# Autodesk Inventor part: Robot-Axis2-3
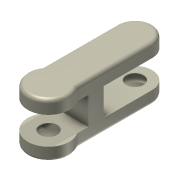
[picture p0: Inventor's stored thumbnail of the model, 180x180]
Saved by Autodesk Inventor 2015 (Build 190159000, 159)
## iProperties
Shininess: 21.0
Length Units: 11269
Angle Units: 11279
Time Units: 11290
Mass Units: 11283
Length Display Precision: 3
Angle Display Precision: 2
Created: 2001-08
Part Number: Robot-Axis2-3
Document SubType Name: ﾓﾃﾞﾘﾝｸﾞ
Designer: Administrator
Density: 1 g/cm^3
Material: Generic
Appearance: Smooth - Ivory
Density: 0.0
Volumn: 0.0
Area: 0.0
PropertySet Name: Model Information
Control State: 0
Master: False
Checked Out: False
Author: Administrator
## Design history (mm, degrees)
node "作業平面1"
sketch "ｽｹｯﾁ2"
  geometry: L1 (0, 0)-(0, 250); L2 (0, 250)-(-50, 250); L3 (-50, 250)-(-50, 33.166); L4 (0, 250)-(50, 250); L5 (50, 250)-(50, 33.166); A1 r 60 centre (0, 0) between (-50, 33.166) and (50, 33.166); A2 r 50 centre (0, 250) between (-50, 250) and (50, 250)
  constraints: 10 end point, 4 point on circle, 2 centre point, 2 perpendicular, 2 tangent, 1 coincident, 1 vertical, 1 other
  dimensions: "d1" = 120 diameter of A1; "d2" = 250 distance of L1.start L1.end; "d3" = 100 diameter of A2
extrude "押し出し1" new body sketch "ｽｹｯﾁ2" distance "d4" = 38; taper "d5" = 0 deg
sketch "ｽｹｯﾁ3"
  geometry: L1 (-50, 250)-(-50, 33.166) reference; L2 (50, 33.166)-(50, 250) reference; L3 (-50, 65)-(50, 65); L4 (50, 65)-(50, 110); L5 (50, 110)-(-50, 110); L6 (-50, 110)-(-50, 65); C1 r 60 at (0, 0); A1 r 60 centre (0, 0) between (-50, 33.166) and (50, 33.166) reference
  constraints: 8 end point, 2 parallel, 2 point on line, 1 centre point, 1 coincident, 1 concentric, 1 horizontal, 1 perpendicular
  dimensions: "d7" = 65 distance from line of L3 C1.centre; "d8" = 140 distance from line of L5 L1.start
extrude "押し出し2" join sketch "ｽｹｯﾁ3" stored distance "d9" = 10; taper "d10" = 0 deg
shell "Shell1" dims "d11" = 2
sketch "Sketch4"
  geometry: A1 r 60 centre (0, 0) between (-50, 33.166) and (50, 33.166) reference
hole "Hole1" sketch "Sketch4" at (0, 0) diameter "d12" = 50; stored, may be unused: countersink angle "d16" = 82 deg, drill point angle "d18" = 118 deg; dims "d13" = 6, "d14" = 4, "d15" = 2, "d17" = 2
sketch "Sketch5"
  geometry: A1 r 60 centre (0, 0) between (-50, 33.166) and (50, 33.166) reference
hole "Hole2" sketch "Sketch5" at (0, 0) diameter "d19" = 50; stored, may be unused: countersink angle "d23" = 82 deg, drill point angle "d25" = 118 deg; dims "d20" = 6, "d21" = 4, "d22" = 2, "d24" = 2
sketch "Sketch6"
  geometry: A1 r 50 centre (0, 250) between (50, 250) and (-50, 250) reference
hole "Hole3" sketch "Sketch6" at (0, 250) diameter "d26" = 50; stored, may be unused: countersink angle "d30" = 82 deg, drill point angle "d32" = 118 deg; dims "d27" = 6, "d28" = 4, "d29" = 2, "d31" = 2
sketch "Sketch7"
  geometry: A1 r 50 centre (0, 0) between (50, 0) and (-50, 0) reference
hole "Hole4" sketch "Sketch7" at (0, 0) diameter "d33" = 50; stored, may be unused: countersink angle "d37" = 82 deg, drill point angle "d39" = 118 deg; dims "d34" = 6, "d35" = 4, "d36" = 2, "d38" = 2
body "Solid1"
fillet "Fillet" dims "d6" = 10
mirror "Mirror"
